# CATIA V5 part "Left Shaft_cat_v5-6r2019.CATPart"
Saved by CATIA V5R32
Part number: Left hand shaft
Bounding box of the stored display mesh (mm): x 0 to 100, y -25 to 25, z -35 to 35
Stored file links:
  D:\PROJECTS\Project 2022\CATIA V5 6R 2022\Resources\Tutorial Files\c16_catia_v5_6r2022_tut\CV joint\Left Shaft_cat_v5-6r2019.CATPart
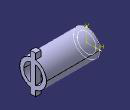
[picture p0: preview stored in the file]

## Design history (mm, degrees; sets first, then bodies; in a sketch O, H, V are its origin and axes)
Body1 (main body)
  Sketch1 on yz-plane, origin (0, 0, 0), H (0, 1, 0), V (0, 0, 1)
    circle A1 centre (0, 0) radius 25
    circle A2 centre (0, 0) radius 17.5
    radius A1 = 25
    radius A2 = 17.5
  Pad1: profile Sketch1, direction (1, 0, 0), length 100
  Sketch2 on end face of Pad1, origin (100, 0, 0), H (0, 1, 0), V (0, 0, 1)
    line L1 (-5, 35) -> (5, 35)
    line L2 (5, 35) -> (5, -35)
    line L3 (5, -35) -> (-5, -35)
    line L4 (-5, -35) -> (-5, 35)
    distance L1 L3 = 70
    distance L4 L2 = 10
    horizontal: L1 H, L3 H
    vertical: L2 V, L4 V
    symmetry: L4 L2 V, L1 L3 H
  Pad2: profile Sketch2, direction (-1, 0, 0), length 10
  Sketch3 on end face of Pad1, origin (100, 0, 0), H (0, 1, 0), V (0, 0, 1)
    line L1 (5, 35) -> (5, -35)
    line L2 (5, -35) -> (-5, -35)
    line L3 (-5, -35) -> (-5, 35)
    line L4 (-5, 35) -> (5, 35)
    length L1 = 70
    length L4 = 10
    vertical: L1 V, L3 V
    horizontal: L2 H, L4 H
    equidistance: L1 L3 O, L2 L4 O
  Pad3: profile Sketch3, direction (-1, 0, 0), length 10
Current feature: Pad2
